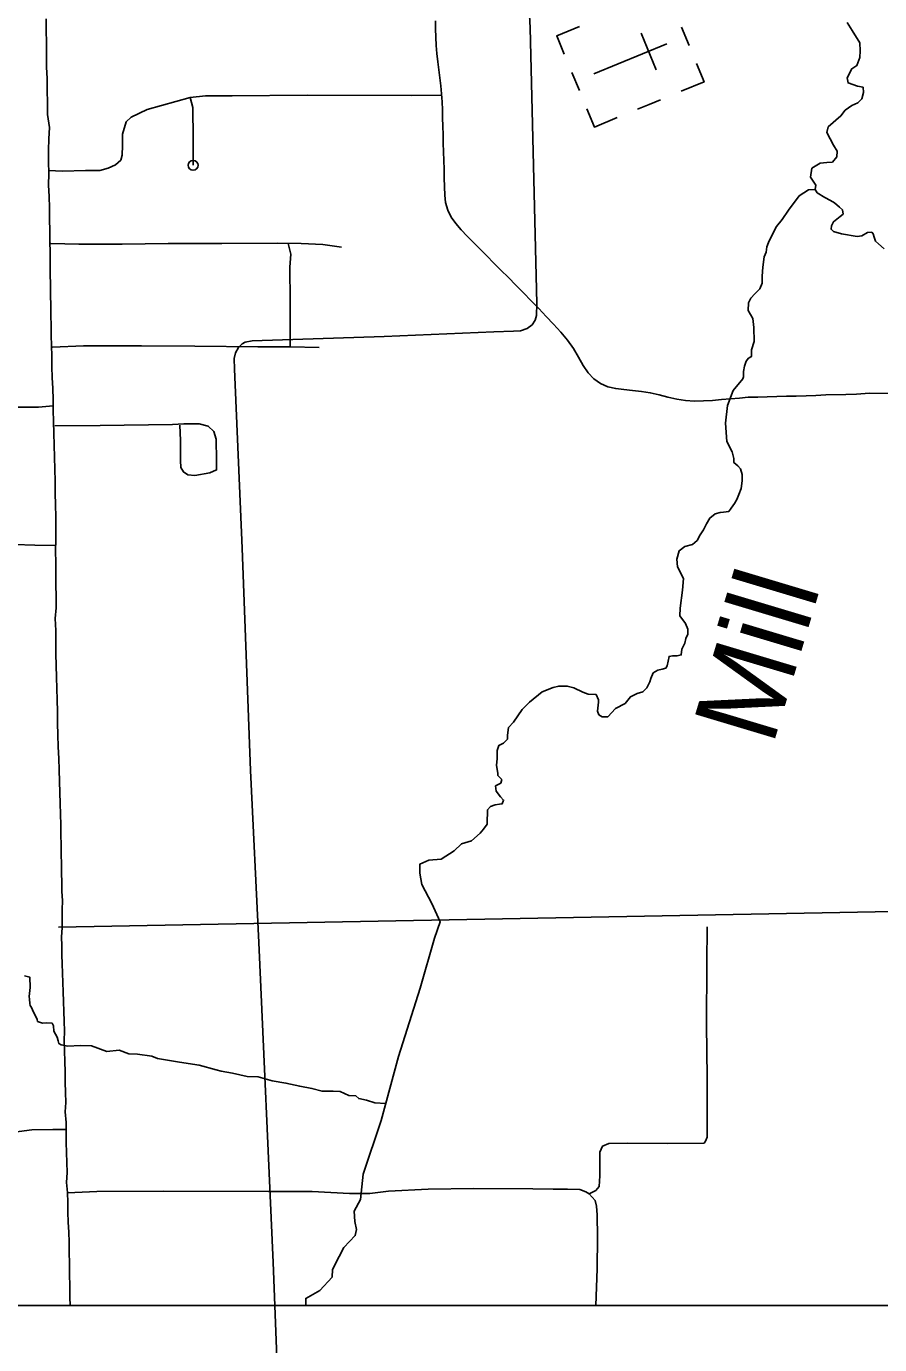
# Model space of a CAD drawing. Extents: x 1367863 to 1368197, y 380048 to 380261.
# Drawn here: x 1368012.13 to 1368028.89, y 380096.1 to 380122.01 of the extents above; entities that cross this region are included whole.
import ezdxf

# ---------------------------------------------------------------- set-up
doc = ezdxf.new("R2010")
doc.units = 0
for name, color, linetype in [('Level 31', 7, 'Continuous'), ('Level 32', 7, 'Continuous'), ('Level 35', 7, 'Continuous'), ('Level 45', 7, 'Continuous'), ('Level 5', 7, 'Continuous'), ('Level 57', 7, 'Continuous'), ('R_Border', 7, 'Continuous'), ('R_No Plot', 7, 'Continuous')]:
    doc.layers.add(name, color=color, linetype=linetype)

msp = doc.modelspace()

# ---------------------------------------------------------------- linework, layer by layer
at = {"layer": 'Level 31'}
for points in [[(1368012.847, 380103.218), (1368012.842, 380103.402), (1368012.836, 380103.582), (1368012.831, 380103.759), (1368012.831, 380103.935), (1368012.826, 380104.117), (1368012.836, 380104.288), (1368012.837, 380104.468), (1368012.839, 380104.648), (1368012.84, 380104.826), (1368012.832, 380105.008), (1368012.828, 380105.187), (1368012.825, 380105.368), (1368012.823, 380105.55), (1368012.82, 380105.735), (1368012.815, 380105.922), (1368012.811, 380106.116), (1368012.808, 380106.316), (1368012.803, 380106.523), (1368012.797, 380106.734), (1368012.792, 380106.949), (1368012.785, 380107.17), (1368012.778, 380107.394), (1368012.769, 380107.622), (1368012.761, 380107.851), (1368012.753, 380108.083), (1368012.746, 380108.316), (1368012.744, 380108.545), (1368012.738, 380108.771), (1368012.731, 380108.996), (1368012.725, 380109.221), (1368012.719, 380109.447), (1368012.713, 380109.678), (1368012.714, 380109.906), (1368012.714, 380110.135), (1368012.701, 380110.37), (1368012.718, 380110.583), (1368012.718, 380110.806), (1368012.713, 380111.031), (1368012.711, 380111.253), (1368012.71, 380111.474), (1368012.709, 380111.696), (1368012.71, 380111.92), (1368012.711, 380112.146), (1368012.711, 380112.374), (1368012.709, 380112.602), (1368012.7, 380112.839), (1368012.697, 380113.072), (1368012.691, 380113.308), (1368012.684, 380113.544), (1368012.678, 380113.782), (1368012.674, 380114.015), (1368012.667, 380114.244), (1368012.659, 380114.467), (1368012.662, 380114.679), (1368012.651, 380114.895), (1368012.639, 380115.109), (1368012.635, 380115.316), (1368012.631, 380115.528), (1368012.625, 380115.737), (1368012.622, 380115.935), (1368012.619, 380116.13), (1368012.617, 380116.328), (1368012.613, 380116.527), (1368012.608, 380116.728), (1368012.605, 380116.932), (1368012.604, 380117.145), (1368012.601, 380117.354), (1368012.598, 380117.567), (1368012.594, 380117.782), (1368012.592, 380118), (1368012.588, 380118.218), (1368012.586, 380118.442), (1368012.584, 380118.666), (1368012.569, 380118.887), (1368012.572, 380119.122), (1368012.569, 380119.352), (1368012.567, 380119.581), (1368012.577, 380119.802), (1368012.589, 380120.023), (1368012.549, 380120.279), (1368012.546, 380120.513), (1368012.543, 380120.748), (1368012.54, 380120.984), (1368012.532, 380121.212), (1368012.528, 380121.451), (1368012.527, 380121.691), (1368012.525, 380121.929), (1368012.521, 380122.162)], [(1368020.337, 380119.033), (1368020.338, 380119.202), (1368020.333, 380119.375), (1368020.328, 380119.546), (1368020.322, 380119.714), (1368020.318, 380119.882), (1368020.314, 380120.048), (1368020.31, 380120.211), (1368020.305, 380120.372), (1368020.298, 380120.53), (1368020.288, 380120.687), (1368020.272, 380120.845), (1368020.255, 380121.002), (1368020.237, 380121.159), (1368020.216, 380121.316), (1368020.198, 380121.475), (1368020.185, 380121.636), (1368020.175, 380121.799), (1368020.17, 380121.96), (1368020.167, 380122.123)], [(1368020.29, 380120.662), (1368019.695, 380120.653), (1368017.647, 380120.661), (1368016.178, 380120.645), (1368015.655, 380120.645), (1368015.353, 380120.613), (1368014.504, 380120.375), (1368014.194, 380120.224), (1368014.091, 380120.137), (1368014.02, 380119.891), (1368014.02, 380119.668), (1368014.012, 380119.478), (1368013.988, 380119.382), (1368013.885, 380119.287), (1368013.742, 380119.224), (1368013.575, 380119.176), (1368013.297, 380119.176), (1368012.845, 380119.168), (1368012.571, 380119.176)], [(1368015.353, 380120.613), (1368015.401, 380120.416), (1368015.409, 380119.804), (1368015.409, 380119.28)], [(1368029.413, 380114.797), (1368028.693, 380114.804), (1368028.437, 380114.782), (1368028.231, 380114.775), (1368027.837, 380114.766), (1368027.642, 380114.758), (1368027.448, 380114.751), (1368027.253, 380114.745), (1368027.062, 380114.741), (1368026.873, 380114.737), (1368026.686, 380114.728), (1368026.502, 380114.725), (1368026.314, 380114.722), (1368026.138, 380114.704), (1368025.961, 380114.688), (1368025.786, 380114.674), (1368025.609, 380114.66), (1368025.433, 380114.649), (1368025.257, 380114.645), (1368025.081, 380114.658), (1368024.907, 380114.685), (1368024.733, 380114.724), (1368024.562, 380114.77), (1368024.388, 380114.808), (1368024.215, 380114.836), (1368024.04, 380114.855), (1368023.872, 380114.87), (1368023.71, 380114.892), (1368023.554, 380114.928), (1368023.41, 380114.991), (1368023.281, 380115.084), (1368023.17, 380115.203), (1368023.071, 380115.345), (1368022.978, 380115.508), (1368022.878, 380115.677), (1368022.761, 380115.842), (1368022.63, 380116.002), (1368022.49, 380116.156), (1368022.344, 380116.309), (1368022.197, 380116.463), (1368022.048, 380116.617), (1368021.899, 380116.771), (1368021.749, 380116.923), (1368021.601, 380117.072), (1368021.456, 380117.219), (1368021.317, 380117.359), (1368021.18, 380117.499), (1368021.047, 380117.635), (1368020.919, 380117.766), (1368020.794, 380117.889), (1368020.675, 380118.011), (1368020.567, 380118.134), (1368020.477, 380118.263), (1368020.41, 380118.399), (1368020.369, 380118.547), (1368020.355, 380118.691), (1368020.345, 380118.857), (1368020.337, 380119.033)], [(1368018.322, 380117.668), (1368017.956, 380117.724), (1368017.528, 380117.74), (1368017.067, 380117.748), (1368015.972, 380117.74), (1368014.916, 380117.74), (1368014.012, 380117.732), (1368013.162, 380117.732), (1368012.615, 380117.74)], [(1368017.274, 380117.744), (1368017.329, 380117.533), (1368017.306, 380117.279), (1368017.313, 380116.612), (1368017.313, 380115.715)], [(1368012.646, 380115.707), (1368013.258, 380115.731), (1368014.393, 380115.731), (1368015.44, 380115.723), (1368016.679, 380115.715), (1368017.313, 380115.715), (1368017.885, 380115.699)], [(1368012.71, 380111.809), (1368012.297, 380111.815), (1368011.493, 380111.841), (1368010.759, 380111.848), (1368010.211, 380111.841), (1368009.78, 380111.815), (1368009.181, 380111.803), (1368008.518, 380111.783), (1368008.029, 380111.764), (1368007.526, 380111.751), (1368007.114, 380111.757)], [(1368023.187, 380099.06), (1368023.318, 380099.13), (1368023.381, 380099.209), (1368023.396, 380099.414), (1368023.396, 380099.879), (1368023.451, 380099.997), (1368023.577, 380100.052), (1368023.94, 380100.06), (1368024.727, 380100.052), (1368025.444, 380100.06), (1368025.475, 380100.099), (1368025.507, 380100.178), (1368025.507, 380100.391), (1368025.507, 380101.352), (1368025.491, 380102.384), (1368025.499, 380103.593), (1368025.507, 380104.31)], [(1368012.996, 380096.865), (1368012.985, 380097.032), (1368012.985, 380097.254), (1368012.984, 380097.476), (1368012.983, 380097.698), (1368012.977, 380097.907), (1368012.971, 380098.109), (1368012.966, 380098.306), (1368012.956, 380098.503), (1368012.95, 380098.701), (1368012.946, 380098.893), (1368012.943, 380099.091), (1368012.921, 380099.284), (1368012.937, 380099.481), (1368012.93, 380099.676), (1368012.921, 380099.876), (1368012.913, 380100.069), (1368012.913, 380100.265), (1368012.917, 380100.464), (1368012.897, 380100.672), (1368012.907, 380100.859), (1368012.903, 380101.057), (1368012.898, 380101.259), (1368012.894, 380101.463), (1368012.89, 380101.666), (1368012.883, 380101.871), (1368012.873, 380102.075), (1368012.881, 380102.262), (1368012.874, 380102.456), (1368012.868, 380102.649), (1368012.862, 380102.841), (1368012.855, 380103.031), (1368012.847, 380103.218)], [(1368012.914, 380100.327), (1368012.651, 380100.327), (1368012.241, 380100.321), (1368011.892, 380100.274), (1368011.596, 380100.267), (1368011.038, 380100.26), (1368010.091, 380100.233), (1368009.453, 380100.2), (1368009.043, 380100.193)], [(1368012.943, 380099.083), (1368013.519, 380099.107), (1368014.834, 380099.115), (1368016.89, 380099.107), (1368017.748, 380099.107), (1368018.48, 380099.068), (1368018.882, 380099.068), (1368019.244, 380099.115), (1368020.024, 380099.154), (1368020.921, 380099.17), (1368022.079, 380099.162), (1368022.478, 380099.154), (1368022.762, 380099.154), (1368023.006, 380099.146), (1368023.124, 380099.099), (1368023.187, 380099.06), (1368023.305, 380098.934), (1368023.329, 380098.823), (1368023.344, 380098.65), (1368023.352, 380098.209), (1368023.344, 380097.587), (1368023.321, 380096.87), (1368023.321, 380096.865)]]:
    msp.add_lwpolyline(points, dxfattribs=at)
msp.add_circle((1368015.409, 380119.28), 0.097, dxfattribs=at)
at = {"layer": 'Level 32'}
msp.add_lwpolyline([(1368012.692, 380114.158), (1368013.583, 380114.166), (1368015.004, 380114.182), (1368015.226, 380114.198), (1368015.528, 380114.198), (1368015.702, 380114.151), (1368015.813, 380114.047), (1368015.861, 380113.896), (1368015.869, 380113.476), (1368015.869, 380113.293), (1368015.734, 380113.237), (1368015.44, 380113.182), (1368015.305, 380113.198), (1368015.218, 380113.253), (1368015.17, 380113.341), (1368015.162, 380113.476), (1368015.162, 380113.873), (1368015.147, 380114.174)], dxfattribs=at)
at = {"layer": 'Level 35'}
for points in [[(1368028.254, 380122.085), (1368028.356, 380121.927), (1368028.504, 380121.687), (1368028.513, 380121.529), (1368028.504, 380121.399), (1368028.448, 380121.242), (1368028.346, 380121.177), (1368028.254, 380121.001), (1368028.272, 380120.899), (1368028.458, 380120.835), (1368028.569, 380120.816), (1368028.578, 380120.714), (1368028.541, 380120.585), (1368028.467, 380120.51), (1368028.346, 380120.455), (1368028.217, 380120.362), (1368028.134, 380120.251), (1368027.884, 380120.038)], [(1368027.884, 380120.038), (1368027.856, 380119.927), (1368027.985, 380119.677), (1368028.059, 380119.557), (1368028.05, 380119.446), (1368027.967, 380119.344), (1368027.856, 380119.334), (1368027.726, 380119.325), (1368027.56, 380119.223), (1368027.532, 380119.047), (1368027.643, 380118.89), (1368027.624, 380118.807), (1368027.495, 380118.797), (1368027.31, 380118.677), (1368027.106, 380118.399), (1368026.976, 380118.214), (1368026.865, 380118.075), (1368026.754, 380117.862), (1368026.708, 380117.76), (1368026.68, 380117.677), (1368026.662, 380117.575), (1368026.625, 380117.482), (1368026.597, 380117.279), (1368026.588, 380117.103), (1368026.588, 380116.964), (1368026.541, 380116.853), (1368026.44, 380116.751), (1368026.365, 380116.667), (1368026.319, 380116.575), (1368026.31, 380116.427), (1368026.402, 380116.269), (1368026.421, 380116.093), (1368026.43, 380115.816), (1368026.375, 380115.65), (1368026.375, 380115.52), (1368026.319, 380115.492), (1368026.273, 380115.427), (1368026.236, 380115.335), (1368026.217, 380115.224), (1368026.217, 380115.122), (1368026.208, 380115.085), (1368026.014, 380114.853), (1368025.903, 380114.557), (1368025.866, 380114.214), (1368025.893, 380113.853), (1368025.995, 380113.649), (1368026.032, 380113.52), (1368026.032, 380113.436), (1368026.106, 380113.371), (1368026.162, 380113.316), (1368026.19, 380113.205), (1368026.19, 380113.075), (1368026.171, 380112.927), (1368026.125, 380112.807), (1368026.088, 380112.714), (1368026.041, 380112.631), (1368025.977, 380112.538), (1368025.93, 380112.473), (1368025.829, 380112.464), (1368025.764, 380112.455), (1368025.662, 380112.427), (1368025.56, 380112.344), (1368025.495, 380112.232), (1368025.431, 380112.112), (1368025.366, 380112.019), (1368025.31, 380111.908), (1368025.218, 380111.825), (1368025.069, 380111.788), (1368024.958, 380111.705), (1368024.912, 380111.538), (1368024.921, 380111.39), (1368025.042, 380111.158), (1368025.023, 380110.927), (1368024.977, 380110.572), (1368024.968, 380110.424), (1368025.079, 380110.276), (1368025.125, 380110.165), (1368025.125, 380110.063), (1368025.088, 380109.979), (1368025.069, 380109.887), (1368025.007, 380109.766), (1368024.998, 380109.655), (1368024.915, 380109.637), (1368024.822, 380109.637), (1368024.758, 380109.627), (1368024.739, 380109.535), (1368024.721, 380109.442), (1368024.693, 380109.396), (1368024.619, 380109.377), (1368024.535, 380109.359), (1368024.443, 380109.303), (1368024.397, 380109.192), (1368024.378, 380109.127), (1368024.322, 380109.007), (1368024.239, 380108.933), (1368024.128, 380108.896), (1368023.998, 380108.831), (1368023.897, 380108.701), (1368023.702, 380108.6), (1368023.554, 380108.442), (1368023.443, 380108.442)], [(1368027.624, 380118.807), (1368027.669, 380118.74), (1368027.817, 380118.647), (1368027.929, 380118.591), (1368028.004, 380118.544), (1368028.106, 380118.46), (1368028.162, 380118.405), (1368028.18, 380118.321), (1368028.115, 380118.274), (1368027.985, 380118.172), (1368027.948, 380118.088), (1368027.938, 380118.023), (1368027.985, 380117.976), (1368028.143, 380117.93), (1368028.45, 380117.883), (1368028.543, 380117.893), (1368028.655, 380117.958), (1368028.739, 380117.967), (1368028.767, 380117.93), (1368028.785, 380117.865), (1368028.813, 380117.79), (1368028.869, 380117.734), (1368028.981, 380117.641)], [(1368023.443, 380108.442), (1368023.378, 380108.479), (1368023.35, 380108.553), (1368023.369, 380108.729), (1368023.369, 380108.775), (1368023.323, 380108.877), (1368023.165, 380108.887), (1368023.064, 380108.924), (1368022.888, 380109.007), (1368022.758, 380109.044), (1368022.591, 380109.044), (1368022.48, 380109.016), (1368022.267, 380108.933), (1368022.018, 380108.729), (1368021.869, 380108.581), (1368021.703, 380108.331), (1368021.601, 380108.229), (1368021.582, 380108.081), (1368021.582, 380107.998), (1368021.508, 380107.924), (1368021.416, 380107.877), (1368021.379, 380107.775), (1368021.379, 380107.618), (1368021.37, 380107.479), (1368021.397, 380107.331), (1368021.397, 380107.285), (1368021.471, 380107.21), (1368021.453, 380107.136), (1368021.351, 380107.081), (1368021.36, 380106.979), (1368021.444, 380106.868), (1368021.508, 380106.803), (1368021.481, 380106.729), (1368021.425, 380106.72), (1368021.342, 380106.71), (1368021.249, 380106.673), (1368021.194, 380106.609), (1368021.194, 380106.497), (1368021.184, 380106.451), (1368021.184, 380106.331), (1368021.11, 380106.229), (1368021.046, 380106.155), (1368020.876, 380106), (1368020.677, 380105.941), (1368020.538, 380105.802), (1368020.279, 380105.643), (1368020.041, 380105.623), (1368019.862, 380105.543), (1368019.862, 380105.364), (1368019.902, 380105.146), (1368020.1, 380104.768), (1368020.259, 380104.412), (1368020.148, 380104.088), (1368019.87, 380103.106), (1368019.444, 380101.764), (1368019.102, 380100.504), (1368018.75, 380099.448), (1368018.695, 380098.953), (1368018.574, 380098.721), (1368018.583, 380098.518), (1368018.62, 380098.36), (1368018.592, 380098.24), (1368018.37, 380098.008), (1368018.278, 380097.832), (1368018.148, 380097.573), (1368018.139, 380097.425), (1368017.9, 380097.164), (1368017.622, 380097.005), (1368017.622, 380096.865)], [(1368012.1, 380103.349), (1368012.199, 380103.322), (1368012.205, 380103.117), (1368012.189, 380102.943), (1368012.194, 380102.887), (1368012.199, 380102.805), (1368012.205, 380102.764), (1368012.235, 380102.728), (1368012.251, 380102.677), (1368012.343, 380102.488), (1368012.353, 380102.452), (1368012.45, 380102.416), (1368012.522, 380102.426), (1368012.64, 380102.416), (1368012.665, 380102.365), (1368012.67, 380102.257), (1368012.737, 380102.145), (1368012.757, 380102.073), (1368012.773, 380102.017), (1368012.814, 380101.991), (1368012.947, 380101.965), (1368013.192, 380101.976), (1368013.412, 380101.971), (1368013.714, 380101.863), (1368013.955, 380101.889), (1368014.149, 380101.817), (1368014.318, 380101.807), (1368014.595, 380101.771), (1368014.712, 380101.725), (1368015.142, 380101.648), (1368015.526, 380101.592), (1368015.864, 380101.499), (1368015.961, 380101.474), (1368016.181, 380101.433), (1368016.473, 380101.366), (1368016.688, 380101.361), (1368016.959, 380101.284), (1368017.23, 380101.238), (1368017.502, 380101.177), (1368017.742, 380101.136), (1368017.942, 380101.08), (1368018.157, 380101.08), (1368018.3, 380101.075), (1368018.469, 380100.998), (1368018.607, 380100.987), (1368018.663, 380100.936), (1368018.817, 380100.906), (1368018.976, 380100.854), (1368018.981, 380100.854), (1368019.193, 380100.841)]]:
    msp.add_lwpolyline(points, dxfattribs=at)
at = {"layer": 'Level 45'}
msp.add_lwpolyline([(1368012.66, 380114.555), (1368012.369, 380114.524), (1368011.194, 380114.524), (1368010.313, 380114.492)], dxfattribs=at)
at = {"layer": 'Level 5'}
msp.add_lwpolyline([(1368033.345, 380104.694), (1368012.765, 380104.306)], dxfattribs=at)
at = {"layer": 'Level 57'}
for p, q in [((1368024.208, 380121.88), (1368024.505, 380121.159)), ((1368025.149, 380121.636), (1368025.001, 380121.994)), ((1368024.715, 380121.669), (1368023.28, 380121.077)), ((1368023.997, 380121.373), (1368023.997, 380121.373)), ((1368023.997, 380121.373), (1368023.997, 380121.373)), ((1368022.848, 380121.107), (1368022.996, 380120.748)), ((1368024.367, 380120.476), (1368024.14, 380120.382)), ((1368024.367, 380120.476), (1368024.588, 380120.567))]:
    msp.add_line(p, q, dxfattribs=at)
for points in [[(1368022.699, 380121.468), (1368022.551, 380121.826), (1368023, 380122.011)], [(1368025.296, 380121.279), (1368025.444, 380120.92), (1368024.995, 380120.735)], [(1368023.739, 380120.217), (1368023.291, 380120.032), (1368023.143, 380120.391)]]:
    msp.add_lwpolyline(points, dxfattribs=at)
at = {"layer": 'R_Border'}
msp.add_lwpolyline([(1368017.069, 380095.505), (1368016.982, 380097.715), (1368016.698, 380104.002), (1368016.533, 380107.387), (1368016.372, 380111.755), (1368016.222, 380115.274), (1368016.215, 380115.482), (1368016.244, 380115.594), (1368016.297, 380115.697), (1368016.371, 380115.773), (1368016.43, 380115.801), (1368016.57, 380115.83), (1368019.164, 380115.915), (1368021.316, 380116.008), (1368021.704, 380116.019), (1368021.842, 380116.029), (1368021.972, 380116.072), (1368022.07, 380116.145), (1368022.124, 380116.234), (1368022.151, 380116.326), (1368022.163, 380116.565), (1368022.031, 380121.983), (1368021.909, 380124.203)], dxfattribs=at)
at = {"layer": 'R_No Plot'}
msp.add_lwpolyline([(1367959.444, 380177.46), (1368103.344, 380177.46), (1368103.344, 380096.865), (1367959.444, 380096.865)], close=True, dxfattribs=at)

# ---------------------------------------------------------------- texts
at = {"layer": 'Level 35'}
msp.add_text('Mill', height=1.6394, rotation=73.2954, dxfattribs=at).set_placement((1368026.79, 380107.845))

doc.saveas('drawing.dxf')
